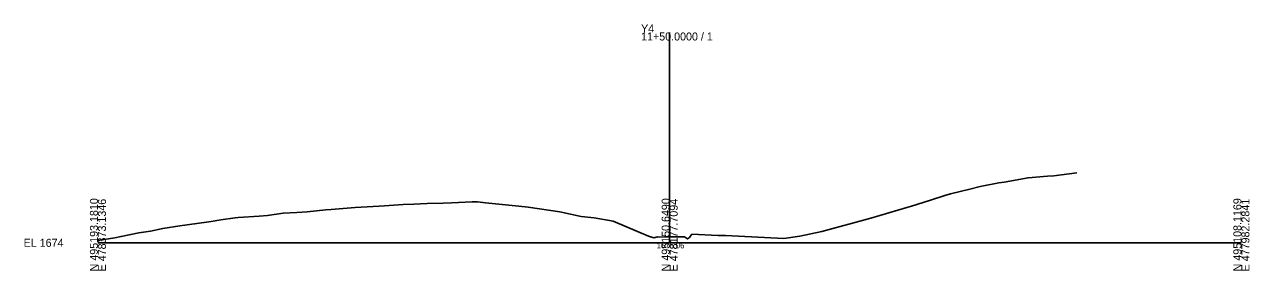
# Model space of a CAD drawing. Extents: x -26 to 403, y -10 to 5108.
# Drawn here: x -25.7 to 402.8, y 1490.3 to 1576.4 of the extents above; entities that cross this region are included whole.
import ezdxf

# ---------------------------------------------------------------- set-up
doc = ezdxf.new("R2010")
doc.units = 0
for name, color, linetype in [('Exist Cross Section Cell', 7, 'Continuous'), ('Exist XS Center Line Elevation Label', 7, 'Continuous'), ('Exist XS Ground Line', 7, 'Continuous')]:
    doc.layers.add(name, color=color, linetype=linetype)

msp = doc.modelspace()

# ---------------------------------------------------------------- linework, layer by layer
at = {"layer": 'Exist Cross Section Cell'}
for p, q in [((200, 1500), (200, 1573.62)), ((0, 1500), (200, 1500)), ((200, 1500), (400, 1500))]:
    msp.add_line(p, q, dxfattribs=at)
at = {"layer": 'Exist XS Ground Line'}
msp.add_lwpolyline([(0, 1500.79), (5.94, 1501.76), (8.12, 1502.25), (14.35, 1503.46), (18.35, 1504.13), (22.75, 1504.96), (28.59, 1505.9), (31.16, 1506.27), (38.82, 1507.31), (39.57, 1507.43), (42.98, 1507.99), (47.97, 1508.8), (49.06, 1508.92), (56.38, 1509.3), (59.3, 1509.62), (64.79, 1510.34), (69.53, 1510.58), (73.19, 1510.87), (79.77, 1511.53), (81.6, 1511.69), (90.01, 1512.37), (98.41, 1512.78), (100.24, 1512.89), (106.82, 1513.39), (110.48, 1513.56), (115.22, 1513.78), (120.71, 1513.9), (123.63, 1514.02), (130.95, 1514.4), (132.79, 1514.34), (135.59, 1513.96), (147.26, 1512.84), (150.47, 1512.5), (161.6, 1510.84), (169.05, 1509.24), (173.54, 1508.72), (180.21, 1507.61), (192.57, 1502.38), (194.42, 1501.79), (195.69, 1502.14), (195.89, 1502.01), (198.74, 1502.07), (200, 1502.06), (205.14, 1502.05), (206.26, 1501.34), (206.9, 1501.86), (207.79, 1503.02), (216.93, 1502.6), (219.52, 1502.54), (239.96, 1501.52), (245.5, 1502.36), (253.18, 1503.91), (270.36, 1508.6), (283.02, 1512.34), (284.61, 1512.79), (290.84, 1514.82), (296.26, 1516.53), (298.3, 1517.09), (304.96, 1518.73), (308.57, 1519.69), (315.2, 1520.97), (316.98, 1521.22), (325.41, 1522.78), (332.19, 1523.35), (334.42, 1523.5), (342.49, 1524.54)], dxfattribs=at)

# ---------------------------------------------------------------- texts
at = {"layer": 'Exist Cross Section Cell'}
for s, p in [('Y4', (190, 1573.62)), ('11+50.0000 / 1', (190, 1570.82)), ('EL 1674', (-26, 1498.6))]:
    msp.add_text(s, height=2.8, dxfattribs=at).set_placement(p)
for s, p in [('N 495193.1810', (0, 1490)), ('E 478373.1346', (2.8, 1490)), ('N 495150.6490', (200, 1490)), ('E 478177.7094', (202.8, 1490)), ('N 495108.1169', (400, 1490)), ('E 477982.2841', (402.8, 1490))]:
    msp.add_text(s, height=2.8, rotation=90, dxfattribs=at).set_placement(p)
at = {"layer": 'Exist XS Center Line Elevation Label'}
msp.add_text('1676.06', height=2, dxfattribs=at).set_placement((195.46, 1498.06))

doc.saveas('drawing.dxf')
